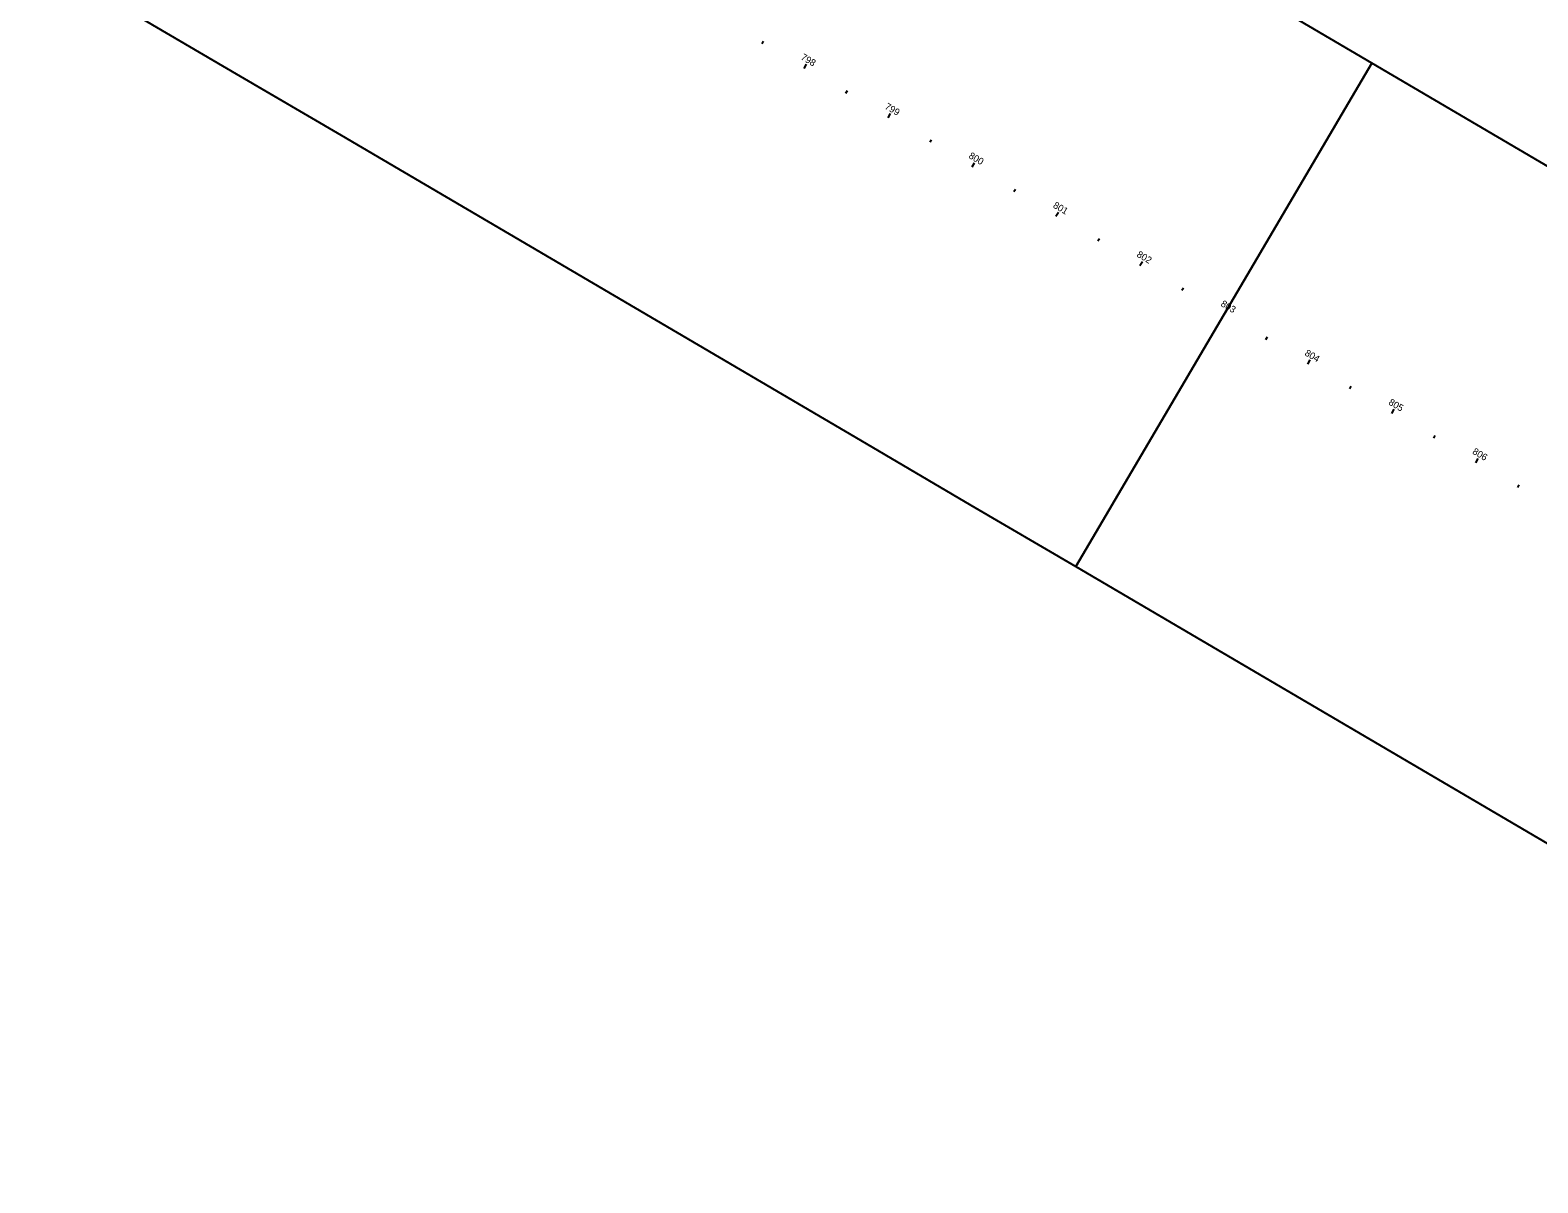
# Model space of a CAD drawing. Extents: x 75725 to 90554, y 518585 to 527848.
# Drawn here: x 81595 to 83143, y 524495 to 525680 of the extents above; entities that cross this region are included whole.
import ezdxf

# ---------------------------------------------------------------- set-up
doc = ezdxf.new("R2010")
doc.units = 0
doc.layers.add('GE_P_Alignment_100_Stations', color=7, linetype='Continuous')
doc.layers.add('SH_Named_Boundary', color=7, linetype='Continuous')

msp = doc.modelspace()

# ---------------------------------------------------------------- linework, layer by layer
at = {"layer": 'GE_P_Alignment_100_Stations'}
for p, q in [((82346.1, 525665.7), (82347.6, 525668.3)), ((82389.2, 525640.4), (82391.8, 525644.7)), ((82432.3, 525615), (82433.9, 525617.6)), ((82475.5, 525589.7), (82478, 525594)), ((82518.6, 525564.4), (82520.1, 525567)), ((82561.7, 525539.1), (82564.2, 525543.4)), ((82604.8, 525513.7), (82606.3, 525516.3)), ((82647.9, 525488.4), (82650.4, 525492.7)), ((82691, 525463.1), (82692.5, 525465.7)), ((82734.1, 525437.8), (82736.7, 525442.1)), ((82777.2, 525412.4), (82778.8, 525415)), ((82820.3, 525387.1), (82822.9, 525391.4)), ((82863.5, 525361.8), (82865, 525364.4)), ((82906.6, 525336.5), (82909.1, 525340.8)), ((82949.7, 525311.1), (82951.2, 525313.7)), ((82992.8, 525285.8), (82995.3, 525290.1)), ((83035.9, 525260.5), (83037.4, 525263.1)), ((83079, 525235.2), (83081.6, 525239.5)), ((83122.1, 525209.8), (83123.6, 525212.4))]:
    msp.add_line(p, q, dxfattribs=at)
at = {"layer": 'SH_Named_Boundary'}
for points in [[(81888.6, 526280), (81594.5, 525757), (81700.3, 525696.8), (81806.2, 525634.9), (81914, 525571.6), (82021.7, 525508.3), (82129.5, 525445), (82237.3, 525381.7), (82345.1, 525318.4), (82452.9, 525255.1), (82560.6, 525191.7), (82668.4, 525128.4), (82972.3, 525645.8), (82864.5, 525709.1), (82756.8, 525772.4), (82649, 525835.7), (82541.2, 525899), (82433.4, 525962.3), (82325.6, 526025.7), (82217.9, 526089), (82110.1, 526152.3), (82000.1, 526216.5)], [(82972.3, 525645.8), (82668.4, 525128.4), (82776.2, 525065.1), (82884, 525001.8), (82991.8, 524938.5), (83099.5, 524875.2), (83207.3, 524811.9), (83315.1, 524748.5), (83422.9, 524685.2), (83530.7, 524621.9), (83638.4, 524558.6), (83746.2, 524495.3), (84050.1, 525012.6), (83942.3, 525075.9), (83834.6, 525139.3), (83726.8, 525202.6), (83619, 525265.9), (83511.2, 525329.2), (83403.4, 525392.5), (83295.7, 525455.8), (83187.9, 525519.1), (83080.1, 525582.5)]]:
    msp.add_lwpolyline(points, close=True, dxfattribs=at)

# ---------------------------------------------------------------- texts
at = {"layer": 'GE_P_Alignment_100_Stations'}
for s, p in [('798', (82385.2, 525650)), ('799', (82471.5, 525599.3)), ('800', (82557.6, 525548.7)), ('801', (82644.3, 525497.8)), ('802', (82730.2, 525447.3)), ('803', (82816.5, 525396.6)), ('804', (82902.7, 525346)), ('805', (82988.8, 525295.4)), ('806', (83074.9, 525244.8))]:
    msp.add_text(s, height=7, rotation=329.5684, dxfattribs=at).set_placement(p)

doc.saveas('drawing.dxf')
